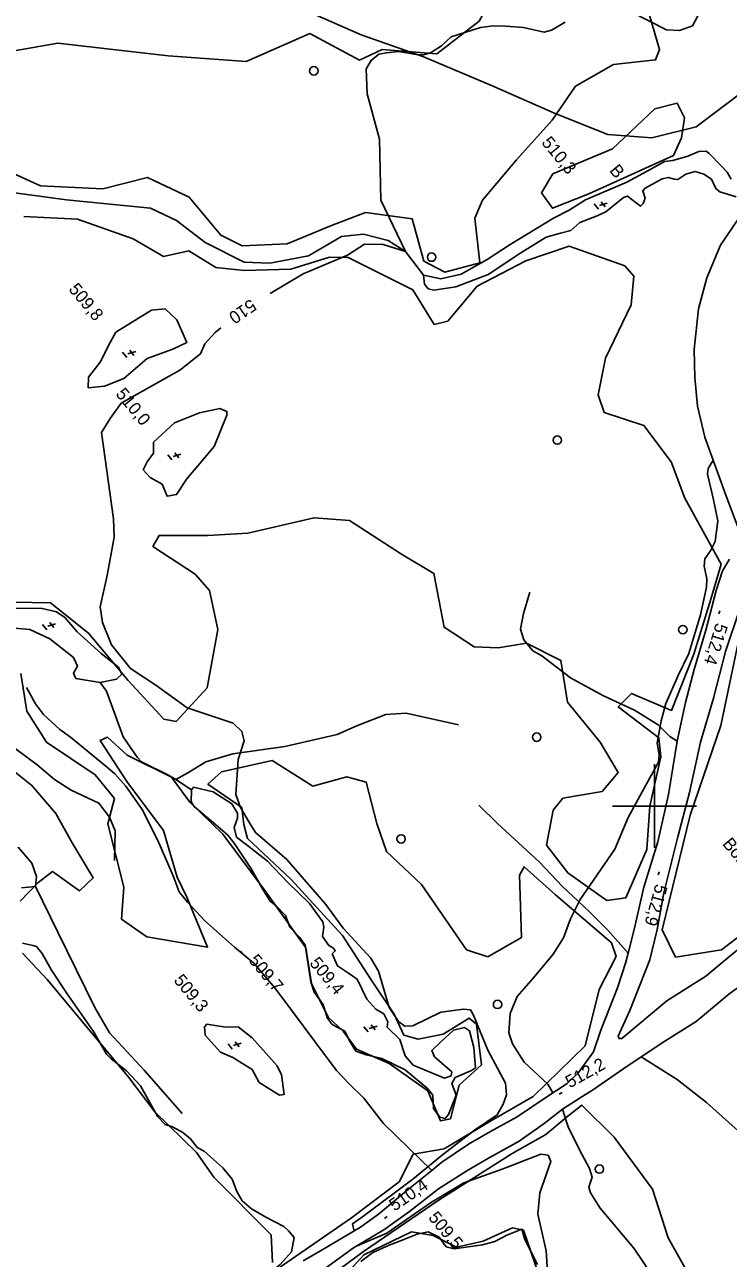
# Model space of a CAD drawing. Extents: x 347312 to 350503, y 6073086 to 6076432.
# Drawn here: x 348749.9 to 348917.6, y 6075692.2 to 6075986.2 of the extents above; entities that cross this region are included whole.
import ezdxf

# ---------------------------------------------------------------- set-up
doc = ezdxf.new("R2010")
doc.units = 0
for name, color, linetype in [('Level 1', 7, 'Continuous'), ('Level 2', 7, 'Continuous'), ('Level 21', 7, 'Continuous'), ('Level 22', 7, 'Continuous'), ('Level 3', 7, 'Continuous'), ('Level 36', 7, 'Continuous'), ('Level 4', 7, 'Continuous'), ('Level 44', 7, 'Continuous'), ('Level 61', 7, 'Continuous')]:
    doc.layers.add(name, color=color, linetype=linetype)

msp = doc.modelspace()

# ---------------------------------------------------------------- linework, layer by layer
at = {"layer": 'Level 1'}
for points in [[(348912.52, 6075992.54), (348909, 6075985.94), (348905.91, 6075984.87), (348902.85, 6075985.02), (348894.4, 6075989.31)], [(348878.73, 6075986.85), (348875.46, 6075984.92), (348875.46, 6075984.92), (348873.67, 6075984.47), (348868.76, 6075985.57), (348864.53, 6075985.88), (348861.6, 6075985.96), (348858.55, 6075985.53), (348851.57, 6075983.35), (348849.2, 6075981.18), (348846.58, 6075979.48), (348844.93, 6075979.02), (348843.18, 6075979.15), (348839.1, 6075979.8)], [(348808.43, 6075922.14), (348816.25, 6075926.85), (348826.82, 6075931.29), (348830.92, 6075933.95), (348835.33, 6075933.87), (348840.66, 6075932.19), (348834.75, 6075944.36), (348834.47, 6075958.96), (348831.5, 6075969.76), (348831.31, 6075975.67), (348832.48, 6075977.69), (348834.34, 6075979.16), (348836.13, 6075979.53), (348839.1, 6075979.8)], [(348812.37, 6075787.23), (348804.94, 6075793.68), (348803.47, 6075795.99), (348801.34, 6075799.63), (348800.26, 6075802.72), (348800.8, 6075811.12), (348802.19, 6075815.51), (348801.7, 6075817.73), (348799.58, 6075819.72), (348788.68, 6075823.37), (348781.16, 6075828.84), (348775.12, 6075832.77), (348770.65, 6075838.39), (348768.46, 6075843.78), (348767.94, 6075847.46), (348769.62, 6075854.94), (348771.29, 6075864.05), (348771.12, 6075868.41), (348768.22, 6075889.05), (348770.3, 6075892.35), (348772.94, 6075896.04), (348786.88, 6075903.85), (348791.8, 6075907.79), (348792.88, 6075910.19), (348795.3, 6075912.88), (348796.65, 6075914)], [(348828.41, 6075698.7), (348828.06, 6075700.45), (348830.43, 6075702.12), (348842.38, 6075711.06), (348849.48, 6075716.86), (348857.11, 6075722.74), (348862.52, 6075726.39), (348863.91, 6075728.98), (348864.69, 6075731.2), (348864.5, 6075733.97), (348860.23, 6075741.79), (348856.78, 6075750.35), (348856.14, 6075751.39), (348854.47, 6075751.59), (348849.09, 6075750.88), (348842.39, 6075747.59), (348840.49, 6075747.51), (348838.99, 6075748.68), (348836.75, 6075752), (348834.25, 6075760.68), (348832.36, 6075763.76), (348825.81, 6075770.88), (348821.64, 6075776.51), (348812.37, 6075787.23)], [(348749.4, 6075767.33), (348751.9, 6075766.78), (348752.74, 6075766.5), (348754.11, 6075764.86), (348756.33, 6075760.84), (348760.19, 6075755.03), (348766.33, 6075746.23), (348769.46, 6075740.86), (348770.54, 6075739.75), (348772.36, 6075738.33), (348774.19, 6075736.91), (348777.54, 6075733.3), (348781.63, 6075725.91), (348783.42, 6075724.06), (348785.17, 6075723.52), (348787.58, 6075722.19), (348789.47, 6075720.69), (348791.01, 6075718.64), (348792.67, 6075717.75)], [(348792.67, 6075717.75), (348797.14, 6075713.74), (348799.35, 6075711.05), (348800.45, 6075708.11), (348801.76, 6075705.87), (348803.97, 6075703.98), (348807.41, 6075702.03), (348811.66, 6075699.8), (348812.76, 6075698.76), (348814.14, 6075697.19), (348813.53, 6075693.76), (348810.82, 6075690.76), (348803.59, 6075684.69), (348802.71, 6075682.76), (348802.76, 6075682.69)], [(348874.63, 6075686.48), (348874.13, 6075693.96), (348872.22, 6075702.76), (348872.65, 6075707.77), (348875.28, 6075715.29), (348874.63, 6075716.79), (348872.93, 6075717.02), (348863.69, 6075713.43), (348854.57, 6075710.23), (348846.58, 6075705.41), (348836.23, 6075698.18), (348829.11, 6075695.21), (348829.11, 6075695.23)]]:
    msp.add_lwpolyline(points, dxfattribs=at)
at = {"layer": 'Level 2'}
for points in [[(348913.97, 6075882.36), (348913.44, 6075881.65), (348912.73, 6075880.41), (348912.6, 6075879.1), (348913.94, 6075873.41), (348915.08, 6075867.96), (348914.45, 6075863.05), (348913.35, 6075860.82), (348911.98, 6075858.91), (348911.81, 6075857.18), (348912.46, 6075854.11), (348912.34, 6075852.15), (348910.95, 6075845.57), (348908.13, 6075836.35), (348905.63, 6075831.11), (348902.69, 6075824.46), (348901.55, 6075820.34), (348900.58, 6075815.02), (348901.05, 6075812.22), (348900.95, 6075810.42), (348897.07, 6075803.37), (348893.72, 6075797.29), (348890.56, 6075789.73), (348882.25, 6075777.72), (348879.97, 6075773.13), (348878.32, 6075768.61), (348875.81, 6075764.7), (348875.81, 6075764.7), (348871.18, 6075759.02), (348867.25, 6075754.57), (348865.58, 6075750.54), (348865.3, 6075745.93), (348866.14, 6075743.31), (348868.91, 6075738.97), (348874.56, 6075733.72), (348875.77, 6075731.64)], [(348878.04, 6075727.72), (348878.16, 6075727.51), (348878.87, 6075725.22), (348879.44, 6075723.57)], [(348879.44, 6075723.57), (348882.11, 6075718.08), (348884.5, 6075713.57), (348885.1, 6075711.55), (348884.31, 6075709.17), (348884.76, 6075707.82), (348887.01, 6075704.12), (348895.06, 6075694.62), (348899.8, 6075687.55), (348906.09, 6075680.84), (348910.32, 6075676.8), (348912.58, 6075674.04), (348920.05, 6075663.01), (348924.25, 6075657.09), (348925.18, 6075655.52)]]:
    msp.add_lwpolyline(points, dxfattribs=at)
at = {"layer": 'Level 21'}
for points in [[(348920.08, 6075940.13), (348915.71, 6075933.65), (348912.45, 6075925.85), (348910.46, 6075918.5), (348909.44, 6075908.82), (348909.56, 6075902.1), (348910.19, 6075895.29), (348911.97, 6075887.93), (348916.95, 6075874.1), (348920.53, 6075864.64)], [(348917.82, 6075858.8), (348916.18, 6075856.08), (348914.68, 6075851.39), (348912.21, 6075841.93), (348909.42, 6075832.57), (348907.37, 6075824.65), (348905.37, 6075815.43), (348903.34, 6075802.73), (348900.78, 6075791.47), (348897.45, 6075780.69), (348895.12, 6075770.59), (348893.68, 6075764.97), (348893.12, 6075762.78), (348891.15, 6075756.65), (348887.22, 6075746.56), (348885.42, 6075741.38), (348881.88, 6075736.5), (348879.13, 6075733.84), (348874.35, 6075730.71), (348867.27, 6075725.89), (348860.94, 6075722.44), (348855.63, 6075719.39), (348849.33, 6075715.08), (348846.9, 6075713.13), (348841.37, 6075708.7), (348834.26, 6075702.73), (348829.93, 6075699.6), (348820.43, 6075693.97), (348816.29, 6075691.6)], [(348920.27, 6075846.96), (348916.92, 6075836.83), (348914.01, 6075825.73), (348910.91, 6075815.21), (348908.28, 6075803.22), (348905.54, 6075792.63), (348902.22, 6075779.31), (348900.63, 6075770.58), (348898.86, 6075763.33), (348894.12, 6075751.23), (348891.29, 6075745.14), (348891.53, 6075744.58), (348892.19, 6075744.6), (348902.93, 6075753.58), (348912.22, 6075759.41), (348923.52, 6075768.89)], [(348818.12, 6075687.29), (348828.28, 6075694.74), (348835.52, 6075699.01), (348841.61, 6075703.38), (348848.5, 6075708.79), (348855.28, 6075713.06), (348860.46, 6075716.08), (348867.76, 6075720.1), (348873.71, 6075724.36), (348878.06, 6075727.74), (348882.26, 6075730.47), (348885.19, 6075732.3), (348892.7, 6075737.48), (348896.81, 6075740.19), (348902.47, 6075743.92), (348909.9, 6075748.66), (348917.71, 6075755.14), (348927.05, 6075761.93), (348936.96, 6075769.65), (348944.71, 6075776.54), (348948.23, 6075778.6)]]:
    msp.add_lwpolyline(points, dxfattribs=at)
at = {"layer": 'Level 22'}
for points in [[(348951.98, 6075991.75), (348947.68, 6075988.83), (348943.97, 6075985.89), (348933.28, 6075978.35), (348921.5, 6075970.65), (348909.87, 6075961.88), (348899.3, 6075959.24), (348888.89, 6075960.03), (348876.33, 6075965.02), (348861.15, 6075971.73), (348844.75, 6075978.63), (348830.08, 6075983.81), (348818.52, 6075988.88), (348806.4, 6075996.78), (348796.27, 6076006.79), (348794.58, 6076008.94), (348788.59, 6076016.57), (348781.14, 6076027.16), (348767.81, 6076047.03), (348756.97, 6076062.94), (348746.85, 6076076.76)], [(348905.37, 6075815.43), (348903.6, 6075816.57), (348900.83, 6075819.36), (348895.22, 6075822.87), (348887.68, 6075826.34), (348879.93, 6075830.53), (348873.13, 6075835.82), (348870.95, 6075837.01), (348868.81, 6075839.58), (348868.07, 6075842.18), (348868.78, 6075845.85), (348870.24, 6075850.95)], [(348846.9, 6075713.13), (348841.34, 6075718.52), (348835.45, 6075724.3), (348830.74, 6075730.4), (348827.15, 6075733.88), (348824.18, 6075736.98), (348819.09, 6075743.89), (348813.74, 6075751.02), (348809.52, 6075756.7), (348804.55, 6075762.57), (348799.92, 6075766.39), (348792.76, 6075772.7), (348788.72, 6075777.09), (348786.76, 6075779.52), (348785.35, 6075783.38), (348781.68, 6075791.76), (348777.96, 6075799.19), (348774.03, 6075804.72), (348771.42, 6075807.66), (348769.29, 6075809.49), (348760.87, 6075816.4), (348758.33, 6075818.27), (348754.46, 6075821.82), (348752.55, 6075824.37), (348750.4, 6075828.22)], [(348893.68, 6075764.97), (348888.96, 6075770.35), (348884.44, 6075774.85), (348878.08, 6075780.83), (348872.53, 6075786.66), (348862.55, 6075795.8), (348858.14, 6075800.18)], [(349027.76, 6075560.18), (349024.06, 6075566.6), (349021.08, 6075571.79), (349013.06, 6075584.09), (349004.19, 6075596.88), (348997.71, 6075606.99), (348989.58, 6075620.68), (348977.07, 6075640.52), (348961.66, 6075668.9), (348947.69, 6075690.67), (348939.62, 6075702.14), (348934.53, 6075707.68), (348924.5, 6075718.42), (348912.34, 6075729.35), (348905.37, 6075734.82), (348896.81, 6075740.19)]]:
    msp.add_lwpolyline(points, dxfattribs=at)
at = {"layer": 'Level 3'}
for p, q in [((348885.58, 6075943.5), (348886.6, 6075942.26)), ((348888.68, 6075943.67), (348886.85, 6075943.12)), ((348887.26, 6075943.98), (348888.25, 6075942.77)), ((348773.28, 6075908.14), (348774.3, 6075906.9)), ((348776.38, 6075908.31), (348774.55, 6075907.76)), ((348774.96, 6075908.62), (348775.95, 6075907.41)), ((348785.69, 6075884.2), (348786.68, 6075882.99)), ((348784.01, 6075883.72), (348785.03, 6075882.48)), ((348787.11, 6075883.89), (348785.28, 6075883.34)), ((348915.5, 6075846.53), (348915.27, 6075845.77)), ((348754.22, 6075843.24), (348755.24, 6075842)), ((348757.32, 6075843.41), (348755.49, 6075842.86)), ((348755.9, 6075843.72), (348756.89, 6075842.51)), ((348901.06, 6075784.34), (348900.84, 6075783.57)), ((348801.32, 6075765.37), (348801.83, 6075764.75)), ((348830.77, 6075747.38), (348831.79, 6075746.15)), ((348833.87, 6075747.55), (348832.04, 6075747)), ((348832.45, 6075747.86), (348833.44, 6075746.66)), ((348798.38, 6075743.3), (348799.4, 6075742.06)), ((348801.48, 6075743.47), (348799.65, 6075742.92)), ((348800.06, 6075743.78), (348801.05, 6075742.57)), ((348877.28, 6075731.3), (348877.98, 6075731.69)), ((348835.63, 6075701.73), (348836.29, 6075702.18))]:
    msp.add_line(p, q, dxfattribs=at)
at = {"layer": 'Level 36'}
for centre in [(348818.82, 6075975.22), (348846.87, 6075930.82), (348876.82, 6075887.22), (348906.72, 6075842.04), (348871.91, 6075816.41), (348839.6, 6075792.15), (348862.58, 6075752.72), (348886.85, 6075713.48)]:
    msp.add_circle(centre, 1, dxfattribs=at)
at = {"layer": 'Level 4'}
for points in [[(348844.94, 6075926.56), (348840.66, 6075932.19), (348836.56, 6075934.77), (348830.65, 6075936.3), (348825.43, 6075935.71), (348817.55, 6075931.1), (348808.3, 6075929.41), (348802.26, 6075929.63), (348792.96, 6075934.33), (348786.07, 6075939.55), (348779.88, 6075942.49), (348759.92, 6075944.47), (348743.91, 6075946.59), (348719.52, 6075948.85), (348710.5, 6075949.16), (348706.75, 6075951.3), (348698.63, 6075956.86), (348688.72, 6075967.99), (348684.56, 6075970.08), (348676.9, 6075968.22), (348671.69, 6075968.85)], [(348904.36, 6075953.86), (348907.94, 6075954.89), (348910.57, 6075955.96), (348912.3, 6075956.05), (348912.99, 6075955.49), (348915.84, 6075952.61), (348917.25, 6075951.09), (348918.2, 6075949.41)], [(348919.45, 6075945.2), (348915.51, 6075946.41), (348914.59, 6075947.15), (348913.57, 6075949.38), (348911.72, 6075950.61), (348909.69, 6075951.25), (348907.42, 6075950.63), (348905.5, 6075949.33), (348904.64, 6075949.37), (348903.29, 6075949.82), (348901.83, 6075949.51), (348897.77, 6075947.25), (348897.17, 6075946.61), (348897.75, 6075944.84), (348897.3, 6075943.57), (348896.67, 6075942.97), (348893.54, 6075945.39), (348892.56, 6075945.03), (348888.4, 6075941.64), (348886.34, 6075940.68), (348882.18, 6075939.09), (348880.04, 6075937.16), (348877.56, 6075936.53), (348874.16, 6075935.57), (348868.12, 6075931.82), (348860.35, 6075926.71), (348852.67, 6075923.77), (348847.43, 6075922.94), (348846.07, 6075923.23), (348845.19, 6075924.37), (348844.94, 6075926.56), (348849.11, 6075925.61), (348853.88, 6075926.73), (348860.15, 6075930.29), (348865.6, 6075933.85), (348875.93, 6075940.11), (348879.67, 6075942.03), (348883.5, 6075944.46), (348893.35, 6075948.68), (348899.13, 6075951.76), (348902.37, 6075953.63), (348904.36, 6075953.86)], [(348765.04, 6075899.64), (348765.12, 6075902.25), (348767.92, 6075905.77), (348770.35, 6075910.64), (348771.63, 6075912.9), (348780.18, 6075918.2), (348783.4, 6075918.48), (348786.19, 6075915.85), (348788.55, 6075910.47), (348785.21, 6075908.89), (348779.11, 6075906.67), (348773.57, 6075901.92), (348768.95, 6075900.04), (348765.04, 6075899.64)], [(348780.64, 6075886.76), (348785.59, 6075891.31), (348791.57, 6075893.73), (348796.44, 6075894.77), (348798.1, 6075894.04), (348798.09, 6075893.14), (348795.11, 6075885.71), (348788.55, 6075878.02), (348786.14, 6075874.22), (348783.88, 6075873.85), (348782.67, 6075876.74), (348779.85, 6075878.31), (348778.2, 6075880.09), (348779.13, 6075882.06), (348780.63, 6075884.06), (348780.64, 6075886.76)], [(348746.31, 6075847.19), (348754.12, 6075847.06), (348757.51, 6075846.27), (348759.52, 6075844.94), (348762.41, 6075841.48), (348768.19, 6075836.36), (348772.26, 6075833.13), (348773.09, 6075831.41), (348771.82, 6075830.21), (348767.96, 6075829.41), (348762.13, 6075830.43), (348761.58, 6075831.63), (348762.56, 6075833.34), (348761.6, 6075835.4), (348755.92, 6075839.85), (348751.19, 6075842.08), (348745.8, 6075842.56), (348742.74, 6075842.43), (348742.16, 6075843.3), (348742.77, 6075845.46), (348744.47, 6075846.86), (348746.31, 6075847.19)], [(348789.71, 6075803.88), (348785.92, 6075806.29), (348784.23, 6075807.37), (348777.73, 6075810.54), (348776.72, 6075811.66), (348773.42, 6075816.51), (348769.41, 6075827.37), (348767.96, 6075829.41)], [(348853.25, 6075819.35), (348840.83, 6075822.1), (348835.94, 6075821.8), (348829.2, 6075819.21), (348824.38, 6075817.02), (348811.93, 6075814.21), (348799.5, 6075812.45), (348793.07, 6075810.57), (348788.79, 6075807.92), (348785.92, 6075806.29)], [(348771.32, 6075787.05), (348771.48, 6075794.1), (348770.14, 6075797.34), (348767.64, 6075800.68), (348761.01, 6075803.74), (348757.04, 6075806.32), (348752.92, 6075809.81), (348747.68, 6075813.73), (348744.48, 6075816.11)], [(348823.2, 6075764.78), (348824.42, 6075761.88), (348827.06, 6075760.16), (348829.11, 6075758.7), (348831.43, 6075753.94), (348833.56, 6075751.57), (348835.47, 6075750.45), (348836.45, 6075748.55), (348836.29, 6075747.3), (348839.32, 6075744.39), (348840.57, 6075740.46), (348842.5, 6075738.23), (348849.96, 6075735.1), (348851.5, 6075735.7), (348851.71, 6075736.62), (348847.55, 6075740.24), (348846.91, 6075741.74), (348848.85, 6075743.57), (348852.1, 6075746.57), (348854.75, 6075747.19), (348855.87, 6075746.39), (348856.95, 6075742.47), (348857.33, 6075737.59), (348856.4, 6075736.98), (348852.45, 6075735.28), (348851.66, 6075733.87), (348852.72, 6075731.07), (348850.89, 6075726.47), (348850.1, 6075725.51), (348848.82, 6075725.88), (348847.32, 6075727.94), (348847.2, 6075731.08), (348845.83, 6075732.72), (348840.55, 6075737.14), (348835.03, 6075739.86), (348831.27, 6075740.73), (348828.8, 6075741.61), (348827.33, 6075744), (348826.19, 6075746.36), (348823.21, 6075747.95), (348821.99, 6075749.49), (348821.05, 6075752.7), (348818.89, 6075755.64), (348818.13, 6075758.09), (348816.75, 6075766.8), (348815.49, 6075768.68), (348813.12, 6075771.15), (348812.05, 6075773.87), (348809.76, 6075776.26), (348808.42, 6075777.32), (348806.84, 6075779.84), (348803.83, 6075785.16), (348799.81, 6075791.15), (348798.3, 6075793.05), (348796.47, 6075794.61), (348790.33, 6075799.88), (348789.56, 6075800.98), (348789.71, 6075803.88), (348790.18, 6075804.49), (348794.86, 6075803.41), (348799.32, 6075800.51), (348800.6, 6075798.26), (348800.61, 6075797.07), (348799.84, 6075794.92), (348800.36, 6075792.58), (348803.02, 6075790.57), (348807.82, 6075786.82), (348812.66, 6075781.74), (348817.8, 6075776.76), (348820.98, 6075772.41), (348821.23, 6075771.11), (348820.87, 6075768.93), (348822.4, 6075766.74), (348823.49, 6075766.15), (348823.92, 6075765.45), (348823.2, 6075764.78)], [(348748.42, 6075790.22), (348751.61, 6075786.41), (348752.79, 6075783.18), (348752.49, 6075780.82), (348749.16, 6075780.47)], [(348787.43, 6075726.75), (348778.41, 6075737.01), (348770.18, 6075745.97), (348766.69, 6075751.95), (348757.82, 6075769.91), (348752.49, 6075780.82)], [(348800.78, 6075747.39), (348804.16, 6075744.79), (348810.05, 6075738.1), (348811.09, 6075735.95), (348811.72, 6075731.21), (348810.64, 6075731.06), (348805.81, 6075734.13), (348804.12, 6075737.24), (348799.52, 6075740.03), (348796.59, 6075741.37), (348792.93, 6075745.39), (348792.78, 6075747.38), (348793.33, 6075747.98), (348797.81, 6075747.33), (348800.78, 6075747.39)], [(348872.12, 6075690.75), (348869.12, 6075696.69), (348868.4, 6075699.18), (348864.8, 6075697.7), (348861.94, 6075696.23), (348859.02, 6075695.39), (348852.25, 6075694.44), (348850.36, 6075694.9), (348848.64, 6075697.23), (348846.07, 6075698.49), (348843.42, 6075697.95), (348839.48, 6075696.34), (348836.79, 6075695.31), (348832.88, 6075693.57), (348830.04, 6075691.44)]]:
    msp.add_lwpolyline(points, dxfattribs=at)
at = {"layer": 'Level 44'}
for points in [[(348743.28, 6075979.27), (348757.83, 6075981.79), (348784.14, 6075978.82), (348802.68, 6075977.46), (348817.86, 6075984.1), (348829.72, 6075977.78), (348835.11, 6075980.32), (348848.12, 6075979.3), (348858.17, 6075987.06), (348862.29, 6075994.38), (348867.48, 6075997.35), (348883.18, 6075991.82), (348889.25, 6076002.57), (348897.85, 6076022.01), (348903.94, 6076024.07), (348908.2, 6076016.24), (348897.83, 6075991.72), (348901.19, 6075980.28), (348900.22, 6075977.83), (348890.21, 6075976.7), (348881.14, 6075971.55), (348875.56, 6075963.47), (348867.07, 6075954.01)], [(348904.5, 6075955.06), (348884.33, 6075945.93), (348875.66, 6075942.46), (348873.05, 6075946.14), (348875.76, 6075950.64), (348889.99, 6075956.63), (348900.05, 6075966.19), (348905.41, 6075967.5), (348907.13, 6075963.99), (348906.44, 6075959.22), (348904.5, 6075955.06)], [(348867.07, 6075954.01), (348858.98, 6075944.43), (348857.18, 6075940.1), (348858.4, 6075929.43), (348850.01, 6075927.24), (348845.02, 6075929.83), (348842.28, 6075939.98), (348831.12, 6075941.49), (348823.06, 6075938.38), (348812.45, 6075933.96), (348801.74, 6075933.53), (348796.65, 6075936.04), (348789.15, 6075945.08), (348779.19, 6075949.83), (348768.55, 6075947.12), (348753.72, 6075947.82), (348745.68, 6075951.49)], [(348749.74, 6075940.47), (348762.54, 6075939.88), (348775.76, 6075935.15), (348782.98, 6075930.97), (348789.08, 6075932.3), (348795.5, 6075928.36), (348802.23, 6075927.66), (348813.33, 6075927.92), (348822.58, 6075930.8), (348826.99, 6075930.72), (348842.4, 6075923.01), (348847.45, 6075914.77), (348850.71, 6075915.54), (348857.71, 6075923.9), (348869.33, 6075929.97), (348879.64, 6075933.45), (348892.87, 6075928.72), (348895.02, 6075926.31), (348894.39, 6075919.49), (348888.3, 6075906.78), (348886.59, 6075898.01), (348888, 6075893.79), (348897.46, 6075890.71), (348903.94, 6075882.02), (348907.23, 6075873.37), (348915.83, 6075857.61)], [(348915.83, 6075857.61), (348913.43, 6075849.32), (348909.35, 6075836.2), (348904.01, 6075822.78), (348894.49, 6075826.84), (348891.33, 6075823.62), (348901.04, 6075816.26), (348901.51, 6075811.72), (348898.87, 6075799.93), (348898.16, 6075789.61), (348893.17, 6075778.12), (348888.6, 6075777.48), (348879.3, 6075784.05), (348874.25, 6075790.65), (348875.85, 6075799.03), (348878.16, 6075801.84), (348887.47, 6075803.44), (348891.33, 6075808), (348887.01, 6075815.2), (348879.22, 6075824.75), (348877.68, 6075834.72), (348869.47, 6075838.83), (348862.74, 6075837.73), (348857.02, 6075837.92), (348849.84, 6075842.59), (348847.43, 6075855.42), (348839.68, 6075860.06), (348827.32, 6075868.07), (348818.87, 6075868.69), (348803.06, 6075865.02), (348793.55, 6075864.48), (348781.95, 6075864.46), (348780.47, 6075861.89), (348790.55, 6075855.25), (348793.97, 6075851.33), (348795.99, 6075842.06), (348793.38, 6075828.19), (348786.05, 6075820.16), (348783.05, 6075820.67), (348774.61, 6075829.88), (348765.13, 6075841.23), (348756.08, 6075848.44), (348747.37, 6075848.57)], [(348929.96, 6075793.58), (348934.69, 6075780.14), (348915.95, 6075765.76), (348904.99, 6075763.99), (348901.83, 6075770.49), (348908.46, 6075797.85), (348915.75, 6075819.18), (348919.87, 6075838.93), (348923.61, 6075847.58), (348925.94, 6075847.12), (348923.13, 6075831.76), (348932.65, 6075827.69), (348932.65, 6075822.3), (348933.97, 6075803.93), (348930.31, 6075794.45), (348929.96, 6075793.58)], [(348749, 6075831.61), (348750.47, 6075822.62), (348755.13, 6075815.23), (348766.76, 6075807.45), (348771.34, 6075801.79)], [(348771.34, 6075801.79), (348769.71, 6075795.78), (348773.58, 6075780.67), (348773.03, 6075773), (348779.07, 6075768.85), (348793.5, 6075766.4), (348788.59, 6075778.24), (348786.23, 6075783.05), (348782.98, 6075794.17), (348774.27, 6075805.87), (348767.94, 6075815.62), (348769.66, 6075816.45), (348774.36, 6075812.09), (348784.9, 6075806.88), (348789.29, 6075800.9), (348797.15, 6075793.31), (348807.4, 6075779.58), (348816.95, 6075766.17), (348818.3, 6075757.67), (348822.26, 6075749.68), (348825.82, 6075746.32), (348828.96, 6075742.02), (348836.8, 6075738.6), (348846, 6075732.1), (348848.97, 6075724.94), (348851.4, 6075725.46), (348853.47, 6075733.48), (348858.78, 6075738.34), (348857.53, 6075747.97), (348855.85, 6075749.44), (348849.65, 6075745.65), (348843.69, 6075744.46), (348840.23, 6075745.35), (348837.98, 6075750.39), (348832.48, 6075758.6), (348825.64, 6075769.15), (348813.37, 6075782.56), (348803, 6075792.27), (348802.16, 6075795.63), (348801.7, 6075799.61), (348793.58, 6075805.18), (348796.82, 6075808.16), (348808.92, 6075810.84), (348818.55, 6075804.73), (348826.66, 6075806.95), (348831.32, 6075805.71), (348833.86, 6075795.81), (348836.12, 6075789.13), (348844.45, 6075781.32), (348855.2, 6075765.76), (348860.23, 6075764.07)], [(348748.85, 6075777.34), (348753.05, 6075781.72), (348756.59, 6075784.36), (348762.99, 6075779.76), (348766.25, 6075782.91), (348761.26, 6075791.24), (348757.38, 6075798.23), (348751.66, 6075804.9), (348744.92, 6075810.27)], [(348860.23, 6075764.07), (348868.32, 6075768.67), (348867.8, 6075783.56), (348868.89, 6075785.52), (348876.3, 6075778.91), (348889.75, 6075767.42), (348890.84, 6075764.13), (348886.83, 6075756.3), (348883.44, 6075742.85), (348871.06, 6075730.78), (348861.16, 6075725.07), (348849.87, 6075718.31), (348842.52, 6075717.04), (348839.18, 6075710.44), (348827.8, 6075701.84), (348810.09, 6075689.62)], [(348808.99, 6075691.19), (348808.62, 6075697.79), (348795, 6075711.57), (348790.85, 6075717.44), (348780.97, 6075727.11), (348774.73, 6075735.31), (348764.88, 6075747.1), (348755.26, 6075758.64), (348749.42, 6075764.9)], [(348815.69, 6075682.75), (348830.66, 6075693.83), (348848.69, 6075706.15), (348866.05, 6075717.21), (348874.09, 6075721.68), (348878.92, 6075725.76), (348882.7, 6075728.74), (348890.35, 6075721.06), (348899.46, 6075708.66), (348903.24, 6075697.09), (348911.58, 6075682.24)], [(348872.3, 6075688.51), (348868.73, 6075698.94), (348866.14, 6075699.5), (348859.17, 6075696.27), (348852.77, 6075694.88), (348847.26, 6075697.68), (348842.06, 6075698.48), (348830.76, 6075693.02), (348826.72, 6075688.62)]]:
    msp.add_lwpolyline(points, dxfattribs=at)
at = {"layer": 'Level 61'}
for p, q in [((348900, 6075810), (348900, 6075790)), ((348890, 6075800), (348910, 6075800))]:
    msp.add_line(p, q, dxfattribs=at)

# ---------------------------------------------------------------- texts
at = {"layer": 'Level 1'}
msp.add_text('510', height=3, rotation=214.6948, dxfattribs=at).set_placement((348803.77, 6075920.98))
at = {"layer": 'Level 3'}
for s, rotation, p in [('  510,3', 309.5179, (348871.49, 6075959.76)), ('  509,8', 309.5179, (348758.84, 6075924.82)), ('  510,0', 309.5179, (348770.04, 6075899.84)), ('512,4', 253.0767, (348914.63, 6075843.79)), ('512,9', 254.4672, (348900.25, 6075781.58)), ('509,7', 309.5679, (348803.13, 6075763.13)), ('  509,4', 309.5179, (348816.22, 6075764.2)), ('  509,3', 309.5179, (348783.86, 6075760.1)), ('512,2', 29.1326, (348879.81, 6075732.68)), ('510,4', 34.0086, (348838.03, 6075703.31)), ('  509,5', 309.5179, (348844.51, 6075703.57))]:
    msp.add_text(s, height=3, rotation=rotation, dxfattribs=at).set_placement(p)
at = {"layer": 'Level 44'}
for s, p in [('B', (348889.09, 6075951.39)), ('Bois', (348916, 6075790.94))]:
    msp.add_text(s, height=3, rotation=309.568, dxfattribs=at).set_placement(p)

doc.saveas('drawing.dxf')
